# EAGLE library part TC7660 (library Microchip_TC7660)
TC7660 Charge Pump DC-to-DC Voltage Converter
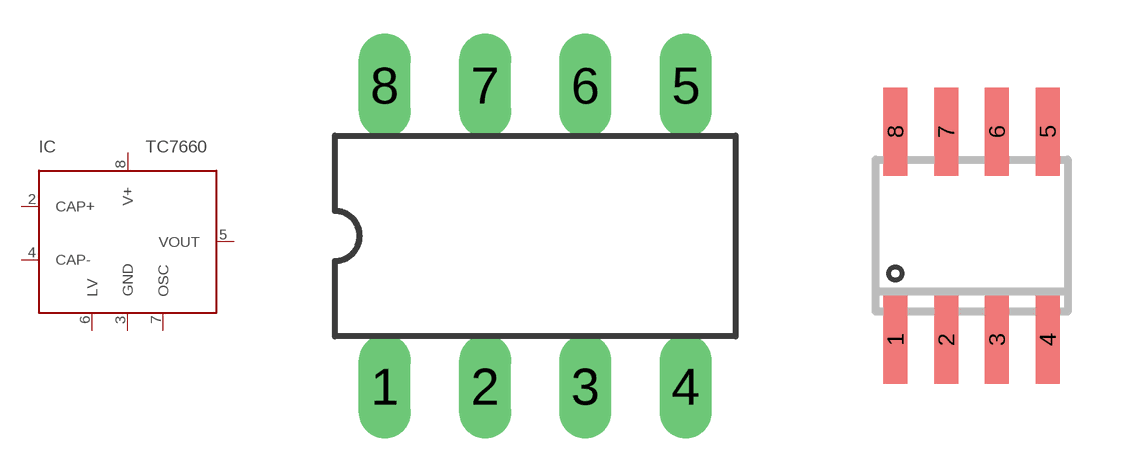
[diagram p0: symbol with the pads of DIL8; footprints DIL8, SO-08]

Designator prefix IC

## TC7660DIL8  [DIL8]
2  CAP+
3  GND
4  CAP-
5  VOUT
6  LV
7  OSC
8  V+

## TC7660SO-08  [SO-08]
Pads as for DIL8

## Footprint DIL8 (pad centres in mm)
DIL8
drill 0.813 long: 1 -3.81,-3.81; 2 -1.27,-3.81; 3 1.27,-3.81; 4 3.81,-3.81; 5 3.81,3.81; 6 1.27,3.81; 7 -1.27,3.81; 8 -3.81,3.81

## Footprint SO-08 (pad centres in mm)
SO-08
smd 0.6 x 2.2: 1 -1.905,-2.6; 2 -0.635,-2.6; 3 0.635,-2.6; 4 1.905,-2.6; 5 1.905,2.6; 6 0.635,2.6; 7 -0.635,2.6; 8 -1.905,2.6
